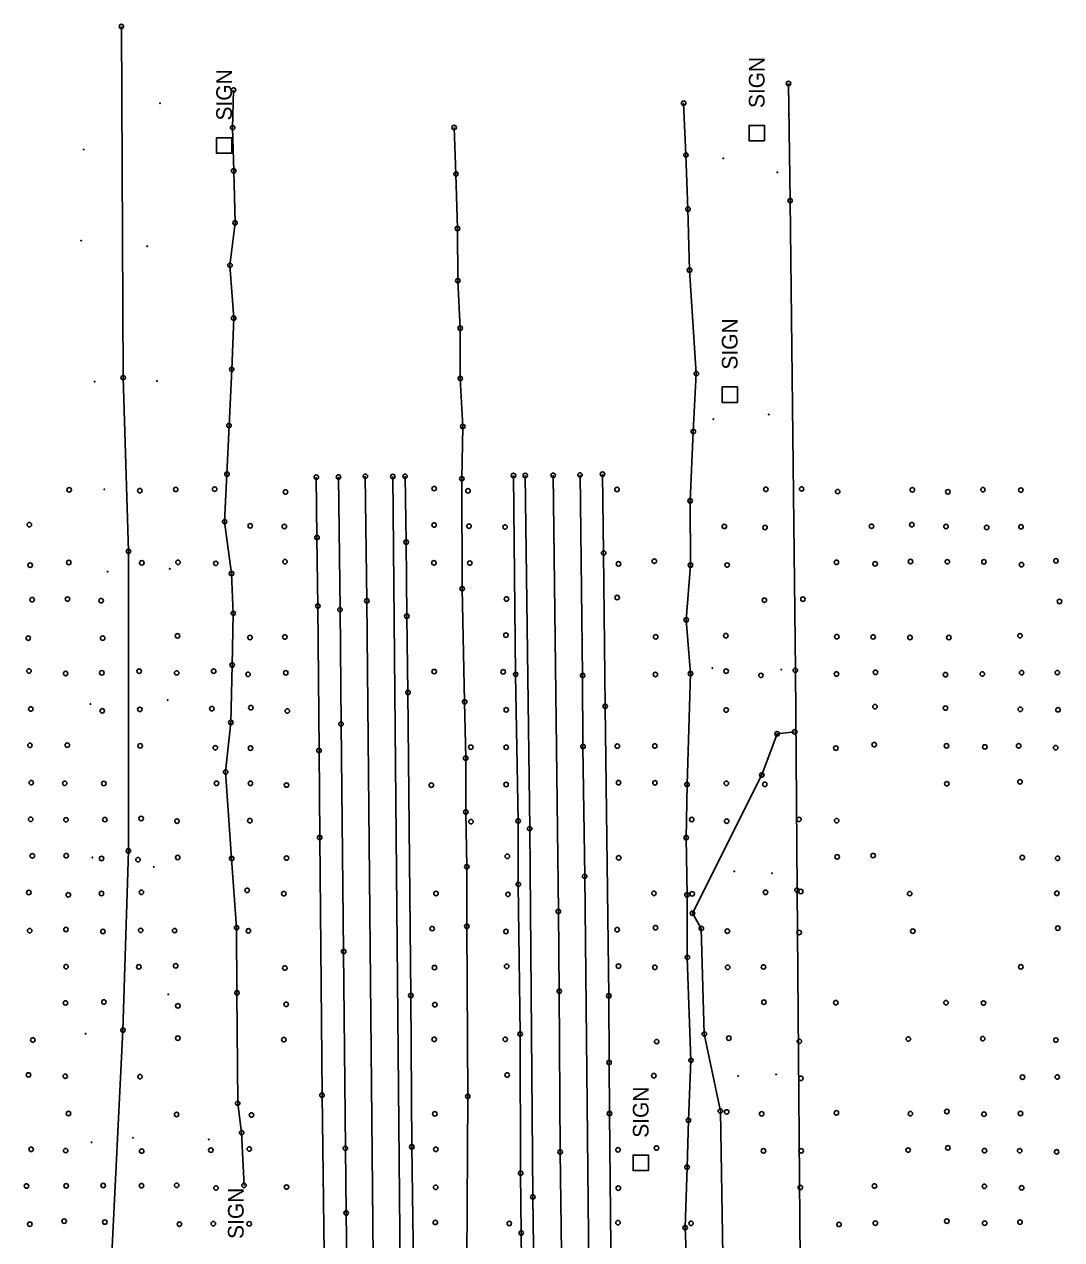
# Model space of a CAD drawing. Extents: x 20503438 to 20508873, y 7964251 to 7984667.
# Drawn here: x 20505218 to 20505682, y 7984124 to 7984667 of the extents above; entities that cross this region are included whole.
import ezdxf

# ---------------------------------------------------------------- set-up
doc = ezdxf.new("R2010")
doc.units = 0
for name, color, linetype in [('SurBreakLine', 7, 'Continuous'), ('SurControl', 7, 'Continuous'), ('SurDrainageArrowDown', 7, 'Continuous'), ('SurDrainageArrowUp', 7, 'Continuous'), ('SurEdgeRoadPaved', 7, 'Continuous'), ('SurEdgeShoulderPaved', 7, 'Continuous'), ('SurFenceWire', 7, 'Continuous'), ('SurPointsNonDTM', 7, 'Continuous'), ('SurRoadPoints', 7, 'Continuous'), ('SurSurveyPoints', 7, 'Continuous'), ('SurTreeLineRight', 7, 'Continuous')]:
    doc.layers.add(name, color=color, linetype=linetype)

msp = doc.modelspace()

# ---------------------------------------------------------------- linework, layer by layer
at = {"layer": 'SurBreakLine'}
for points in [[(20505388.09, 7982786.72), (20505387.46, 7982826.69), (20505386.97, 7982893.61), (20505385.8, 7982999.79), (20505385.32, 7983030.07), (20505384.98, 7983076.27), (20505384.47, 7983119.49), (20505384.1, 7983167.57), (20505382.15, 7983337.32), (20505379.76, 7983573.99), (20505379.24, 7983609.63), (20505378.24, 7983709.76), (20505377.29, 7983778.59), (20505376.87, 7983823.71), (20505376.2, 7983914.92), (20505375.66, 7983955.45), (20505374.47, 7984054.03), (20505371.04, 7984409.5), (20505370.34, 7984465.16)], [(20505462.87, 7983680.32), (20505462, 7983754.37), (20505461.92, 7983763.14), (20505461.43, 7983820.73), (20505460.13, 7983920.56), (20505459.87, 7983956.36), (20505458.96, 7984026.11), (20505458.21, 7984106.73), (20505457.44, 7984163.09), (20505457.01, 7984234.97), (20505456.62, 7984270.6), (20505454.26, 7984465.59)]]:
    msp.add_lwpolyline(points, dxfattribs=at)
at = {"layer": 'SurControl'}
for centre in [(20505278.59, 7984631.93), (20505244.47, 7984611.22), (20505530.35, 7984607.29), (20505554.48, 7984601.04), (20505243.34, 7984570.5), (20505272.84, 7984568.02), (20505249.41, 7984507.48), (20505277.25, 7984507.74), (20505525.86, 7984490.7), (20505550.7, 7984492.79), (20505253.67, 7984459.29), (20505282.95, 7984423.79), (20505255.17, 7984422.51), (20505525.42, 7984379.36), (20505556.24, 7984378.75), (20505247.52, 7984363.35), (20505281.98, 7984365.07), (20505248.33, 7984294.75), (20505275.82, 7984290.47), (20505535.26, 7984288.54), (20505552.05, 7984287.72), (20505282.28, 7984233.55), (20505245.39, 7984215.97), (20505536.97, 7984197.1), (20505553.97, 7984197.78), (20505266.48, 7984169.39), (20505300.38, 7984168.65), (20505248.04, 7984167.4)]:
    msp.add_circle(centre, 0.15, dxfattribs=at)
at = {"layer": 'SurDrainageArrowDown'}
for points in [[(20505316.12, 7984148.17), (20505315.05, 7984171.71), (20505313.31, 7984184.87), (20505312.96, 7984234.23), (20505312.81, 7984263.36), (20505310.59, 7984294.27), (20505307.91, 7984332.98), (20505310.22, 7984355.11), (20505310.8, 7984380.78), (20505311.32, 7984403.86), (20505310.55, 7984421.7), (20505307.45, 7984444.85), (20505308.51, 7984466.08), (20505309.43, 7984487.86), (20505310.64, 7984512.94), (20505311.52, 7984535.88), (20505309.86, 7984559.46), (20505312.13, 7984578.48), (20505311.52, 7984601.68), (20505311.05, 7984620.98), (20505311.47, 7984637.83)], [(20505516.7, 7983964.57), (20505514.28, 7983988.75), (20505514.91, 7984015.06), (20505514.13, 7984039.03), (20505515.08, 7984085.02), (20505513.28, 7984129.28), (20505514.11, 7984156.29), (20505514.76, 7984177.27), (20505515.85, 7984204.03), (20505514.24, 7984250.08), (20505514.12, 7984278.02), (20505513.76, 7984303.59), (20505514.1, 7984327.37), (20505515.67, 7984376.97), (20505513.76, 7984401.01), (20505515.66, 7984425.46), (20505515.53, 7984454.22), (20505516.92, 7984485.15), (20505518.27, 7984511.07), (20505515.23, 7984557.31), (20505514.54, 7984584.59), (20505513.62, 7984608.83), (20505512.59, 7984631.93)]]:
    msp.add_lwpolyline(points, dxfattribs=at)
at = {"layer": 'SurDrainageArrowUp'}
msp.add_lwpolyline([(20505421.16, 7983731.09), (20505419.67, 7983779.95), (20505419.5, 7983832.82), (20505419.46, 7983889.67), (20505419.05, 7983962.92), (20505417.58, 7984039.73), (20505415.76, 7984114.76), (20505416.12, 7984188), (20505415.7, 7984263.99), (20505415.68, 7984290.61), (20505415.27, 7984315.09), (20505415.19, 7984339.17), (20505414.71, 7984364.31), (20505413.6, 7984414.93), (20505413.44, 7984464.07), (20505413.89, 7984487.44), (20505412.77, 7984508.85), (20505412.76, 7984531.37), (20505411.67, 7984552.58), (20505411.51, 7984575.95), (20505410.83, 7984600.27), (20505410.02, 7984621.06)], dxfattribs=at)
at = {"layer": 'SurEdgeRoadPaved'}
for points in [[(20505367.02, 7983649.08), (20505365.92, 7983751.56), (20505365.51, 7983791.53), (20505365.33, 7983812.07), (20505365.03, 7983855.71), (20505364.56, 7983893.31), (20505362.58, 7984070.22), (20505362.33, 7984090.49), (20505361.75, 7984135.8), (20505361.43, 7984164.73), (20505360.65, 7984252.69), (20505359.48, 7984354.42), (20505359.05, 7984405.55), (20505358.33, 7984464.86)], [(20505403.63, 7982474.93), (20505402.88, 7982536.9), (20505402.67, 7982576.67), (20505401.63, 7982665.51), (20505399.87, 7982796.43), (20505397.64, 7982996.42), (20505397.31, 7983043.62), (20505395.75, 7983196.59), (20505394.62, 7983287.56), (20505393.71, 7983393.22), (20505391.47, 7983583.96), (20505391.16, 7983613.2), (20505390.95, 7983649.19), (20505388.69, 7983846.62), (20505387.86, 7983937.63), (20505387.13, 7984000.04), (20505387.09, 7984002.85), (20505386.65, 7984030.88), (20505382.6, 7984465.04)], [(20505449.78, 7983725.38), (20505449.64, 7983752.99), (20505449.04, 7983812.58), (20505447.94, 7983902.43), (20505447.63, 7983935.88), (20505447.17, 7983968.3), (20505446.93, 7983996.29), (20505446.39, 7984036.71), (20505446.17, 7984064.44), (20505445.22, 7984143), (20505443.79, 7984307.66), (20505441.81, 7984465.5)], [(20505484.93, 7982775.73), (20505484.31, 7982835.82), (20505483.21, 7982919), (20505481.67, 7983052.88), (20505480.16, 7983185.03), (20505479.57, 7983233.06), (20505478.99, 7983282.65), (20505478.07, 7983364.47), (20505477.49, 7983427.45), (20505476.34, 7983527.07), (20505475.78, 7983595.33), (20505474.69, 7983687.27), (20505474.16, 7983745.86), (20505473.26, 7983818.48), (20505472.69, 7983886.02), (20505472.06, 7983927.63), (20505471.61, 7983985.32), (20505470.9, 7984047.39), (20505470.84, 7984053.12), (20505468.38, 7984286.35), (20505467.61, 7984344.39), (20505467.44, 7984376.12), (20505466.29, 7984465.77)]]:
    msp.add_lwpolyline(points, dxfattribs=at)
at = {"layer": 'SurEdgeShoulderPaved'}
for points in [[(20505356.33, 7983687.67), (20505355.63, 7983757.41), (20505354.55, 7983828.42), (20505353.53, 7983929.56), (20505353.47, 7983960.72), (20505353.18, 7984002.99), (20505353.04, 7984016.95), (20505352.47, 7984070.78), (20505352.34, 7984082.36), (20505350.99, 7984188.49), (20505349.95, 7984303.65), (20505349.66, 7984342.61), (20505349.12, 7984407.15), (20505348.72, 7984437.82), (20505348.42, 7984464.78)], [(20505396.26, 7983698.73), (20505395.49, 7983760.73), (20505395.13, 7983786.82), (20505394.68, 7983821.97), (20505393.87, 7983937.23), (20505392.66, 7984036.58), (20505392.48, 7984069.7), (20505391.14, 7984165.4), (20505390.7, 7984233.06), (20505389.4, 7984368.52), (20505388.88, 7984402.64), (20505388.62, 7984435.71), (20505388.1, 7984465.16)], [(20505445.01, 7983677.11), (20505444.05, 7983741.95), (20505442.91, 7983871.04), (20505440.02, 7984126.9), (20505439.76, 7984153.63), (20505439.51, 7984215.86), (20505438.71, 7984282.71), (20505438.63, 7984311.09), (20505437.5, 7984376.59), (20505436.53, 7984465.51)], [(20505484.96, 7983655.65), (20505482.47, 7983897.96), (20505482.01, 7983938.92), (20505481.54, 7983978.76), (20505480.77, 7984060.56), (20505480.73, 7984063.33), (20505480.34, 7984091), (20505479.48, 7984180.27), (20505479.28, 7984203.06), (20505479.16, 7984232.92), (20505477.56, 7984362.31), (20505476.85, 7984430.86), (20505476.34, 7984466.08)]]:
    msp.add_lwpolyline(points, dxfattribs=at)
at = {"layer": 'SurFenceWire'}
for points in [[(20505261.33, 7984666.22), (20505262.12, 7984509.28), (20505264.5, 7984431.6), (20505264.46, 7984297.73), (20505262.01, 7984217.56), (20505256.74, 7984111.38), (20505257.38, 7984034.58), (20505258.94, 7983929.81), (20505261.07, 7983745.71)], [(20505559.43, 7984640.78), (20505560.17, 7984588.37), (20505562.54, 7984378.42), (20505563.28, 7984280.23), (20505565.01, 7984077.63), (20505567.76, 7983869.69), (20505568.29, 7983819.98), (20505570.2, 7983612.37), (20505577.97, 7983452.36), (20505588.36, 7983359.69), (20505598.48, 7983268.53), (20505602.02, 7983169.29), (20505604.28, 7983214.9), (20505597.36, 7983079.77), (20505591.48, 7982965.7), (20505583.74, 7982820.12), (20505580.19, 7982701.02)]]:
    msp.add_lwpolyline(points, dxfattribs=at)
at = {"layer": 'SurPointsNonDTM'}
for centre in [(20505261.33, 7984666.22), (20505559.43, 7984640.78), (20505560.17, 7984588.37), (20505262.12, 7984509.28), (20505264.5, 7984431.6), (20505562.54, 7984378.42), (20505554.36, 7984350.05), (20505562.2, 7984350.95), (20505547.55, 7984331.64), (20505264.46, 7984297.73), (20505563.28, 7984280.23), (20505516.56, 7984269.81), (20505520.5, 7984262.99), (20505262.01, 7984217.56), (20505521.83, 7984215.85), (20505529, 7984181.41)]:
    msp.add_circle(centre, 1, dxfattribs=at)
at = {"layer": 'SurRoadPoints'}
for points in [[(20505548.69, 7984618.58), (20505548.69, 7984618.58), (20505548.69, 7984622.01), (20505541.83, 7984622.01), (20505541.83, 7984615.15), (20505548.69, 7984615.15), (20505548.69, 7984618.58)], [(20505310.66, 7984613.02), (20505310.66, 7984613.02), (20505310.66, 7984616.45), (20505303.8, 7984616.45), (20505303.8, 7984609.59), (20505310.66, 7984609.59), (20505310.66, 7984613.02)], [(20505536.62, 7984501.65), (20505536.62, 7984501.65), (20505536.62, 7984505.08), (20505529.76, 7984505.08), (20505529.76, 7984498.22), (20505536.62, 7984498.22), (20505536.62, 7984501.65)], [(20505496.83, 7984158.24), (20505496.83, 7984158.24), (20505496.83, 7984161.67), (20505489.97, 7984161.67), (20505489.97, 7984154.81), (20505496.83, 7984154.81), (20505496.83, 7984158.24)]]:
    msp.add_lwpolyline(points, dxfattribs=at)
at = {"layer": 'SurSurveyPoints'}
for centre in [(20505311.47, 7984637.83), (20505512.59, 7984631.93), (20505311.05, 7984620.98), (20505410.02, 7984621.06), (20505513.62, 7984608.83), (20505311.52, 7984601.68), (20505410.83, 7984600.27), (20505514.54, 7984584.59), (20505312.13, 7984578.48), (20505411.51, 7984575.95), (20505309.86, 7984559.46), (20505411.67, 7984552.58), (20505515.23, 7984557.31), (20505311.52, 7984535.88), (20505412.76, 7984531.37), (20505310.64, 7984512.94), (20505518.27, 7984511.07), (20505412.77, 7984508.85), (20505309.43, 7984487.86), (20505413.89, 7984487.44), (20505516.92, 7984485.15), (20505308.51, 7984466.08), (20505436.53, 7984465.51), (20505441.81, 7984465.5), (20505454.26, 7984465.59), (20505466.29, 7984465.77), (20505476.34, 7984466.08), (20505348.42, 7984464.78), (20505358.33, 7984464.86), (20505370.34, 7984465.16), (20505382.6, 7984465.04), (20505388.1, 7984465.16), (20505413.44, 7984464.07), (20505238.01, 7984459.11), (20505269.56, 7984458.74), (20505285.61, 7984459.29), (20505303, 7984459.39), (20505334.67, 7984458.14), (20505401.08, 7984459.66), (20505416.23, 7984458.68), (20505482.79, 7984459.28), (20505549.3, 7984459.33), (20505565.31, 7984459.51), (20505581.46, 7984458.32), (20505614.82, 7984459.11), (20505630.66, 7984458.23), (20505646.35, 7984459.16), (20505663.28, 7984459), (20505515.53, 7984454.22), (20505307.45, 7984444.85), (20505220.21, 7984443.56), (20505318.91, 7984443.03), (20505334.16, 7984442.72), (20505401.07, 7984443.39), (20505416.65, 7984442.85), (20505432.8, 7984442.47), (20505530.76, 7984442.75), (20505548.99, 7984442.25), (20505596.58, 7984442.82), (20505614.58, 7984443.51), (20505629.86, 7984442.72), (20505648, 7984442.26), (20505663.36, 7984442.6), (20505348.72, 7984437.82), (20505388.62, 7984435.71), (20505476.85, 7984430.86), (20505220.57, 7984425.42), (20505237.8, 7984426.62), (20505270.45, 7984426.47), (20505286.65, 7984426.72), (20505303.49, 7984426.22), (20505334.44, 7984426.98), (20505400.99, 7984426.47), (20505417.01, 7984426.37), (20505483.49, 7984426), (20505499.51, 7984427.22), (20505515.66, 7984425.46), (20505532.06, 7984425.47), (20505580.88, 7984426.68), (20505598.17, 7984426.02), (20505613.98, 7984427.04), (20505630.44, 7984426.96), (20505646.79, 7984426.95), (20505663.58, 7984425.64), (20505678.98, 7984427.37), (20505310.55, 7984421.7), (20505413.6, 7984414.93), (20505221.47, 7984409.99), (20505237.22, 7984410.27), (20505252.29, 7984409.57), (20505349.12, 7984407.15), (20505371.04, 7984409.5), (20505433.46, 7984410.33), (20505482.87, 7984410.95), (20505548.69, 7984409.75), (20505565.9, 7984410.25), (20505680.55, 7984409.21), (20505311.32, 7984403.86), (20505359.05, 7984405.55), (20505388.88, 7984402.64), (20505513.76, 7984401.01), (20505219.7, 7984392.82), (20505252.93, 7984392.81), (20505286.4, 7984393.81), (20505318.81, 7984393.1), (20505334.38, 7984393.31), (20505433.17, 7984394.15), (20505500.11, 7984393.4), (20505531.45, 7984393.91), (20505581.05, 7984393.49), (20505597.29, 7984393.35), (20505613.75, 7984393.11), (20505631.13, 7984393.07), (20505662.92, 7984393.88), (20505310.8, 7984380.78), (20505220.04, 7984378.11), (20505236.39, 7984377), (20505252.6, 7984377.28), (20505269.3, 7984378.02), (20505286.03, 7984377.25), (20505302.56, 7984378.06), (20505317.94, 7984376.6), (20505334.78, 7984377.27), (20505401.1, 7984377.86), (20505431.96, 7984377.72), (20505437.5, 7984376.59), (20505467.44, 7984376.12), (20505499.98, 7984376.55), (20505515.67, 7984376.97), (20505531.58, 7984378.06), (20505547.14, 7984376.15), (20505580.94, 7984376.77), (20505598.35, 7984377.54), (20505629.64, 7984376.45), (20505646.07, 7984376.75), (20505663.63, 7984377.38), (20505679.62, 7984377.4), (20505389.4, 7984368.52), (20505414.71, 7984364.31), (20505477.56, 7984362.31), (20505220.84, 7984361.13), (20505252.77, 7984360.28), (20505269.59, 7984360.95), (20505301.76, 7984361.26), (20505319.2, 7984361.71), (20505335.5, 7984360.23), (20505433.32, 7984360.74), (20505531.64, 7984360.68), (20505598.1, 7984362.16), (20505629.6, 7984361.54), (20505663.09, 7984360.97), (20505679.89, 7984360.79), (20505310.22, 7984355.11), (20505359.48, 7984354.42), (20505220.45, 7984344.88), (20505237.14, 7984344.96), (20505269.7, 7984344.66), (20505303.32, 7984343.81), (20505319.03, 7984343.6), (20505349.66, 7984342.61), (20505417.47, 7984344.03), (20505433.29, 7984344.02), (20505467.61, 7984344.39), (20505482.96, 7984344.52), (20505499.71, 7984344.61), (20505580.64, 7984343.64), (20505597.73, 7984345.16), (20505630.08, 7984344.69), (20505647.18, 7984344.18), (20505662.3, 7984344.67), (20505678.84, 7984343.84), (20505415.19, 7984339.17), (20505307.91, 7984332.98), (20505221.04, 7984328.2), (20505236.01, 7984327.91), (20505253.45, 7984327.81), (20505303.82, 7984327.91), (20505318.99, 7984327.91), (20505335.09, 7984327.11), (20505399.83, 7984327.1), (20505433.25, 7984327.37), (20505483.52, 7984328.2), (20505499.77, 7984328.1), (20505514.1, 7984327.37), (20505531.67, 7984327.9), (20505548.85, 7984327.47), (20505630.24, 7984327.72), (20505662.93, 7984328.54), (20505415.27, 7984315.09), (20505220.77, 7984311.82), (20505236.55, 7984311.62), (20505253.94, 7984311.69), (20505270.17, 7984312.18), (20505286.17, 7984310.98), (20505318.71, 7984311.23), (20505417.58, 7984310.78), (20505438.63, 7984311.09), (20505516.22, 7984311.74), (20505531.85, 7984310.98), (20505564.15, 7984311.77), (20505580.98, 7984311.2), (20505349.95, 7984303.65), (20505443.79, 7984307.66), (20505513.76, 7984303.59), (20505221.54, 7984295.5), (20505236.67, 7984295.54), (20505252.47, 7984294.32), (20505268.74, 7984293.75), (20505286.51, 7984294.74), (20505310.59, 7984294.27), (20505335.14, 7984294.48), (20505433.83, 7984295.29), (20505483.57, 7984294.6), (20505581.2, 7984295.02), (20505597.28, 7984295.6), (20505663.94, 7984294.73), (20505679.72, 7984294.36), (20505415.68, 7984290.61), (20505468.38, 7984286.35), (20505438.71, 7984282.71), (20505219.93, 7984279.07), (20505237.59, 7984278.02), (20505252.4, 7984278.64), (20505270.27, 7984279.16), (20505317.52, 7984280.04), (20505333.91, 7984278.6), (20505401.91, 7984278.65), (20505434.07, 7984278.24), (20505499.32, 7984278.71), (20505514.12, 7984278.02), (20505516.38, 7984278.49), (20505549.17, 7984279.17), (20505564.94, 7984279.56), (20505613.63, 7984278.61), (20505679.39, 7984278.74), (20505456.62, 7984270.6), (20505220.34, 7984262.05), (20505236.54, 7984262.58), (20505253.07, 7984261.68), (20505269.92, 7984262.15), (20505285.1, 7984262.06), (20505312.81, 7984263.36), (20505318.09, 7984261.94), (20505400.24, 7984262.96), (20505415.7, 7984263.99), (20505433.18, 7984261.69), (20505482.86, 7984262.5), (20505500, 7984263.35), (20505532.12, 7984261.82), (20505564.21, 7984261.2), (20505615, 7984261.82), (20505679.81, 7984263.13), (20505360.65, 7984252.69), (20505514.24, 7984250.08), (20505236.6, 7984245.94), (20505269.11, 7984245.84), (20505285.59, 7984246.34), (20505334.39, 7984245.36), (20505401.24, 7984245.53), (20505433.52, 7984246.11), (20505483.51, 7984246.15), (20505499.76, 7984245.62), (20505532.25, 7984245.62), (20505548.29, 7984245.82), (20505663.3, 7984245.84), (20505312.96, 7984234.23), (20505390.7, 7984233.06), (20505457.01, 7984234.97), (20505479.16, 7984232.92), (20505236.34, 7984229.73), (20505253.51, 7984230.13), (20505286.57, 7984228.42), (20505334.94, 7984229.09), (20505401.38, 7984228.96), (20505548.47, 7984230.05), (20505580.59, 7984229.86), (20505629.87, 7984229.86), (20505646.61, 7984229.66), (20505439.51, 7984215.86), (20505221.74, 7984213.17), (20505286.53, 7984213.97), (20505333.89, 7984213.33), (20505401.13, 7984213.45), (20505432.88, 7984213.47), (20505500.57, 7984212.44), (20505532.81, 7984213.95), (20505564.31, 7984212.56), (20505613.02, 7984213.58), (20505646.27, 7984213.75), (20505678.97, 7984213.12), (20505479.28, 7984203.06), (20505515.85, 7984204.03), (20505219.78, 7984197.55), (20505236.24, 7984196.94), (20505269.67, 7984196.77), (20505433.7, 7984197.52), (20505499.3, 7984197.22), (20505565.01, 7984196), (20505664.03, 7984196.54), (20505679.57, 7984196.62), (20505350.99, 7984188.49), (20505313.31, 7984184.87), (20505416.12, 7984188), (20505237.71, 7984180.27), (20505285.99, 7984179.87), (20505319.47, 7984179.62), (20505401.38, 7984180.12), (20505479.48, 7984180.27), (20505531.85, 7984181.01), (20505547.48, 7984180.13), (20505580.88, 7984180.6), (20505613.94, 7984180.24), (20505630.22, 7984181.22), (20505646.82, 7984180.02), (20505663.12, 7984180.28), (20505514.76, 7984177.27), (20505315.05, 7984171.71), (20505220.98, 7984164.3), (20505236.43, 7984163.71), (20505270.39, 7984163.49), (20505301.32, 7984163.91), (20505318.47, 7984164.44), (20505361.43, 7984164.73), (20505391.14, 7984165.4), (20505401.86, 7984164.29), (20505457.44, 7984163.09), (20505483.26, 7984164.04), (20505500.44, 7984164.85), (20505548.3, 7984163.58), (20505565.14, 7984163.6), (20505612.92, 7984163.95), (20505630.69, 7984164.93), (20505647.06, 7984163.7), (20505662.78, 7984163.65), (20505679.27, 7984163.14), (20505514.11, 7984156.29), (20505439.76, 7984153.63), (20505218.94, 7984147.86), (20505236.62, 7984147.99), (20505253.21, 7984148.08), (20505270.34, 7984148.02), (20505286.02, 7984148.21), (20505303.59, 7984146.99), (20505316.12, 7984148.17), (20505335.11, 7984147.41), (20505401.77, 7984147.31), (20505483.41, 7984146.89), (20505564.77, 7984147.2), (20505597.92, 7984147.89), (20505647.01, 7984147.72), (20505663.64, 7984147.06), (20505445.22, 7984143), (20505361.75, 7984135.8), (20505220.39, 7984130.79), (20505235.74, 7984132.15), (20505253.94, 7984131.75), (20505287.25, 7984130.8), (20505302.44, 7984131.07), (20505318.46, 7984130.96), (20505401.65, 7984131.6), (20505434.67, 7984131.14), (20505483.25, 7984131.49), (20505513.28, 7984129.28), (20505515.92, 7984131.22), (20505582.03, 7984130.71), (20505598.27, 7984131.28), (20505630.19, 7984132.15), (20505647.13, 7984131.27), (20505662.93, 7984131.69), (20505440.02, 7984126.9)]:
    msp.add_circle(centre, 1, dxfattribs=at)
at = {"layer": 'SurTreeLineRight'}
msp.add_lwpolyline([(20505562.2, 7984350.95), (20505554.36, 7984350.05), (20505547.55, 7984331.64), (20505516.56, 7984269.81), (20505520.5, 7984262.99), (20505521.83, 7984215.85), (20505529, 7984181.41), (20505530.21, 7984107.66), (20505529.77, 7984072.16), (20505529.18, 7984036.24), (20505536.72, 7984014.44), (20505537.92, 7984002.41), (20505535.71, 7983989.08), (20505528.05, 7983976.3), (20505527.31, 7983934.11), (20505525.03, 7983882.56), (20505527.31, 7983859.79), (20505531.72, 7983837.17), (20505544.05, 7983828.15), (20505574.38, 7983820.74)], dxfattribs=at)

# ---------------------------------------------------------------- texts
at = {"layer": 'SurRoadPoints'}
for p in [(20505548.76, 7984629.79), (20505310.73, 7984624.23), (20505536.69, 7984512.86), (20505496.9, 7984169.45), (20505315.96, 7984124.24)]:
    msp.add_text('SIGN', height=6.995, rotation=90, dxfattribs=at).set_placement(p)

doc.saveas('drawing.dxf')
